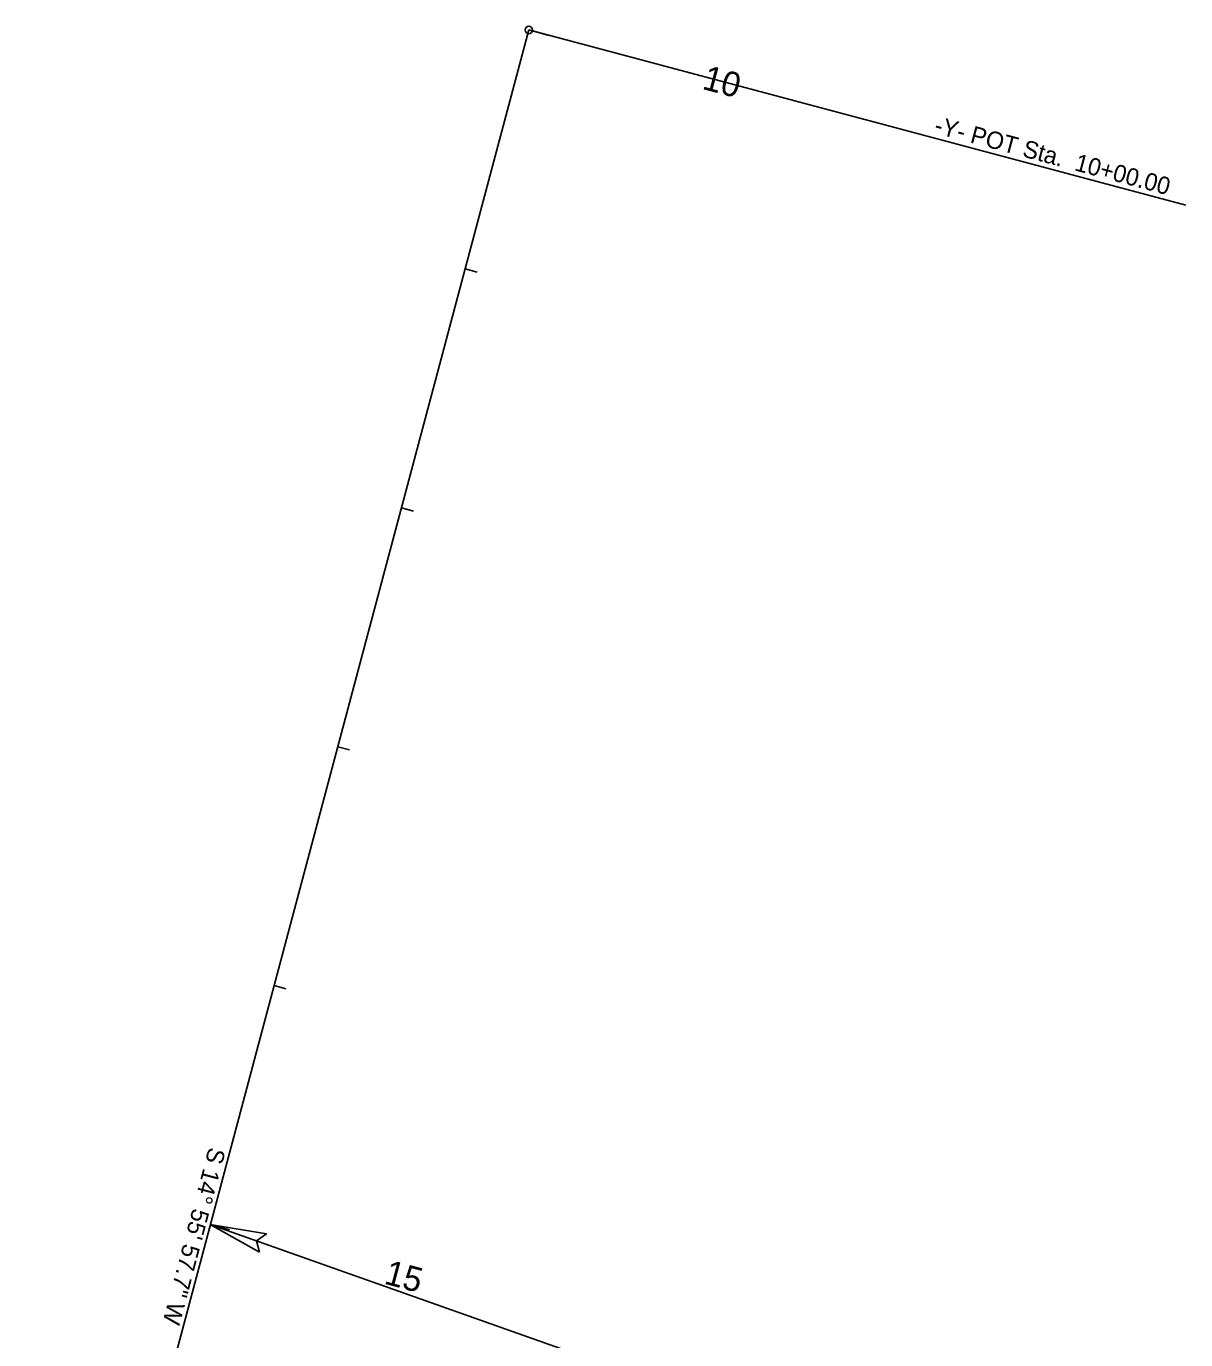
# Model space of a CAD drawing. Extents: x 1778969 to 1790720, y 807089 to 817794.
# Drawn here: x 1782997 to 1783466, y 815493 to 816024 of the extents above; entities that cross this region are included whole.
import ezdxf

# ---------------------------------------------------------------- set-up
doc = ezdxf.new("R2010")
doc.units = 0
for name, color, linetype in [('Prop Horizontal Alignment', 7, 'Continuous'), ('Prop Horizontal Alignment Direction Label', 7, 'Continuous'), ('Prop Horizontal Alignment Station Label', 7, 'Continuous'), ('Prop Horizontal Alignment Tick Label', 7, 'Continuous'), ('Prop Horizontal Alignment Tick Large', 7, 'Continuous'), ('Prop Horizontal Alignment Tick Small', 7, 'Continuous'), ('Prop Terminator CELL', 7, 'Continuous')]:
    doc.layers.add(name, color=color, linetype=linetype)

msp = doc.modelspace()

# ---------------------------------------------------------------- linework, layer by layer
at = {"layer": 'Prop Horizontal Alignment'}
msp.add_line((1783199.88, 816022.55), (1782996.6, 815260.29), dxfattribs=at)
at = {"layer": 'Prop Horizontal Alignment Station Label'}
for p, q in [((1783201.33, 816022.16), (1783465.6, 815951.68)), ((1783071.04, 815539.43), (1783429.79, 815412.68))]:
    msp.add_line(p, q, dxfattribs=at)
msp.add_circle((1783199.88, 816022.55), 1.5, dxfattribs=at)
at = {"layer": 'Prop Horizontal Alignment Tick Large'}
for p, q in [((1783199.88, 816022.55), (1783207.61, 816020.48)), ((1783071.04, 815539.43), (1783078.77, 815537.37))]:
    msp.add_line(p, q, dxfattribs=at)
at = {"layer": 'Prop Horizontal Alignment Tick Small'}
for p, q in [((1783174.11, 815925.92), (1783178.94, 815924.63)), ((1783148.35, 815829.3), (1783153.18, 815828.01)), ((1783122.58, 815732.68), (1783127.41, 815731.39)), ((1783096.81, 815636.05), (1783101.64, 815634.76))]:
    msp.add_line(p, q, dxfattribs=at)
at = {"layer": 'Prop Terminator CELL'}
msp.add_lwpolyline([(1783090.96, 815528.28), (1783071.04, 815539.43), (1783093.71, 815535.66), (1783089.66, 815532.85)], close=True, dxfattribs=at)

# ---------------------------------------------------------------- texts
at = {"layer": 'Prop Horizontal Alignment Direction Label'}
msp.add_text('S 14%%d 55\' 57.7" W', height=7, rotation=255.1913, dxfattribs=at).set_placement((1783070.52, 815571.07))
at = {"layer": 'Prop Horizontal Alignment Station Label'}
msp.add_text('-Y- POT Sta.  10+00.00', height=7, rotation=345.0673, dxfattribs=at).set_placement((1783363.46, 815980.99))
at = {"layer": 'Prop Horizontal Alignment Tick Label'}
for s, p in [('10', (1783269.61, 815998.78)), ('15', (1783140.93, 815515.62))]:
    msp.add_text(s, height=10, rotation=345.0673, dxfattribs=at).set_placement(p)

doc.saveas('drawing.dxf')
